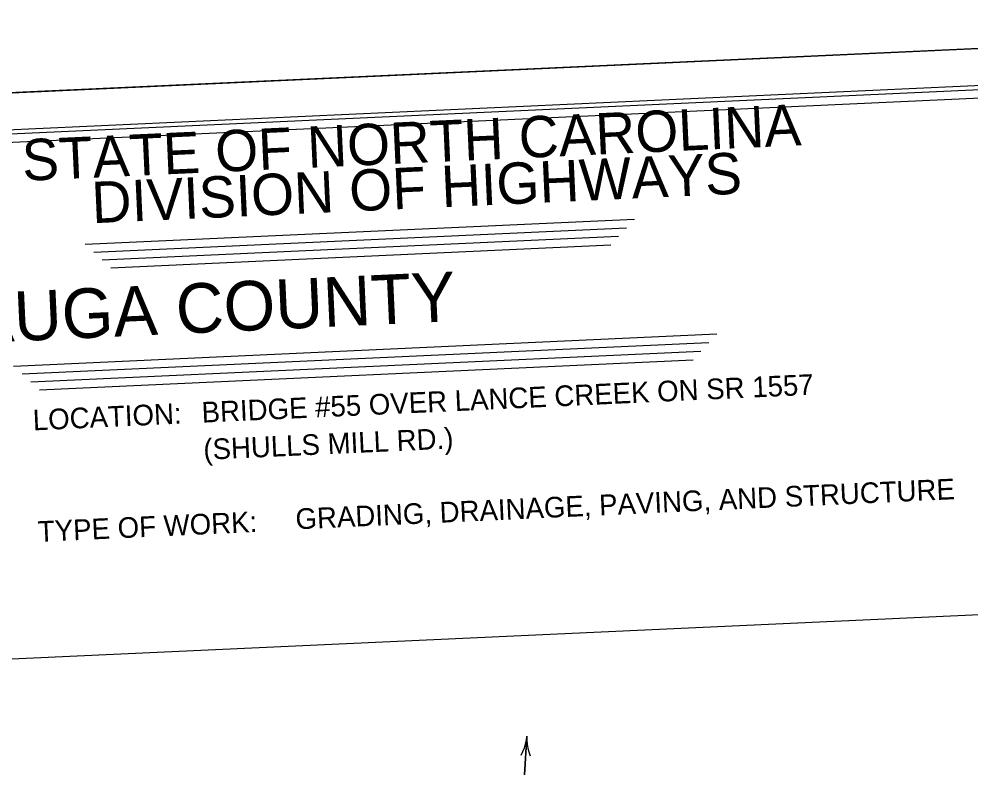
# Model space of a CAD drawing. Extents: x 1190067 to 1192950, y 891516 to 893460.
# Drawn here: x 1192542.6 to 1192773, y 893192.4 to 893376.5 of the extents above; entities that cross this region are included whole.
import ezdxf

# ---------------------------------------------------------------- set-up
doc = ezdxf.new("R2010")
doc.units = 0
for name, color, linetype in [('Default', 7, 'Continuous'), ('Scratch_Level_3', 7, 'Continuous'), ('Sheet Cutting Line CELL', 7, 'Continuous'), ('Sheet Data Field CELL', 7, 'Continuous'), ('Sheet Plot Border Inside CELL', 7, 'Continuous'), ('Sheet Plot Border Outside CELL', 7, 'Continuous'), ('Sheet Title CELL', 7, 'Continuous'), ('Sheet Title Data Points CELL', 7, 'Continuous')]:
    doc.layers.add(name, color=color, linetype=linetype)

msp = doc.modelspace()

# ---------------------------------------------------------------- linework, layer by layer
at = {"layer": 'Default'}
msp.add_line((1192665.24, 893198.34), (1192665.24, 893198.34), dxfattribs=at)
msp.add_lwpolyline([(1192664.17, 893198.41), (1192664.59, 893199.27), (1192664.94, 893200.17), (1192665.21, 893201.11), (1192665.41, 893202.06), (1192665.5, 893203.02), (1192664.97, 893193.67), (1192665.5, 893203.02), (1192665.48, 893202.06), (1192665.57, 893201.09), (1192665.74, 893200.13), (1192665.99, 893199.19), (1192666.31, 893198.28)], dxfattribs=at)
at = {"layer": 'Scratch_Level_3'}
msp.add_lwpolyline([(1192415.45, 893028.46), (1192896.45, 893050.47), (1192887.89, 893237.54), (1192406.89, 893215.53)], close=True, dxfattribs=at)
at = {"layer": 'Sheet Cutting Line CELL'}
msp.add_line((1192257.43, 893345.67), (1192930.33, 893376.46), dxfattribs=at)
at = {"layer": 'Sheet Plot Border Inside CELL'}
msp.add_lwpolyline([(1192282.33, 892915.34), (1192948.23, 892945.8), (1192928.94, 893367.4), (1192263.04, 893336.94)], close=True, dxfattribs=at)
at = {"layer": 'Sheet Plot Border Outside CELL'}
msp.add_lwpolyline([(1192930.33, 893376.46), (1192257.43, 893345.67), (1192277.54, 892906.14), (1192950.44, 892936.92)], close=True, dxfattribs=at)
at = {"layer": 'Sheet Title CELL'}
for p, q in [((1192558.59, 893321.99), (1192691.55, 893328.08)), ((1192560.68, 893320.09), (1192689.65, 893325.98)), ((1192562.77, 893318.18), (1192687.74, 893323.9)), ((1192564.86, 893316.27), (1192685.83, 893321.81)), ((1192541.26, 893292.53), (1192711.48, 893300.31)), ((1192543.35, 893290.63), (1192709.58, 893298.23)), ((1192545.44, 893288.71), (1192707.67, 893296.14)), ((1192547.53, 893286.81), (1192705.76, 893294.05))]:
    msp.add_line(p, q, dxfattribs=at)
for points in [[(1192920, 893365.97), (1192328.61, 893338.92)], [(1192918.09, 893363.88), (1192350.69, 893337.92)]]:
    msp.add_lwpolyline(points, dxfattribs=at)
at = {"layer": 'Sheet Title Data Points CELL'}
for p, q in [((1192626.72, 893302.41), (1192626.72, 893302.41)), ((1192675.68, 893282.88), (1192675.68, 893282.88))]:
    msp.add_line(p, q, dxfattribs=at)

# ---------------------------------------------------------------- texts
at = {"layer": 'Sheet Data Field CELL'}
for s, height, p in [('        WATAUGA COUNTY       ', 12, (1192459.7, 893294.77)), ('BRIDGE #55 OVER LANCE CREEK ON SR 1557  ', 5, (1192586.92, 893278.82)), ('(SHULLS MILL RD.)                       ', 5, (1192587.34, 893269.83)), ('GRADING, DRAINAGE, PAVING, AND STRUCTURE', 5, (1192609.64, 893253.02))]:
    msp.add_text(s, height=height, rotation=2.6195, dxfattribs=at).set_placement(p)
at = {"layer": 'Sheet Title CELL'}
for s, height, p in [('STATE OF NORTH CAROLINA', 10, (1192543.56, 893337.3)), ('DIVISION OF HIGHWAYS', 10, (1192560.4, 893327.06)), ('LOCATION: ', 5, (1192546.06, 893276.95)), ('TYPE OF WORK:', 5, (1192547.29, 893249.98))]:
    msp.add_text(s, height=height, rotation=2.6195, dxfattribs=at).set_placement(p)

doc.saveas('drawing.dxf')
